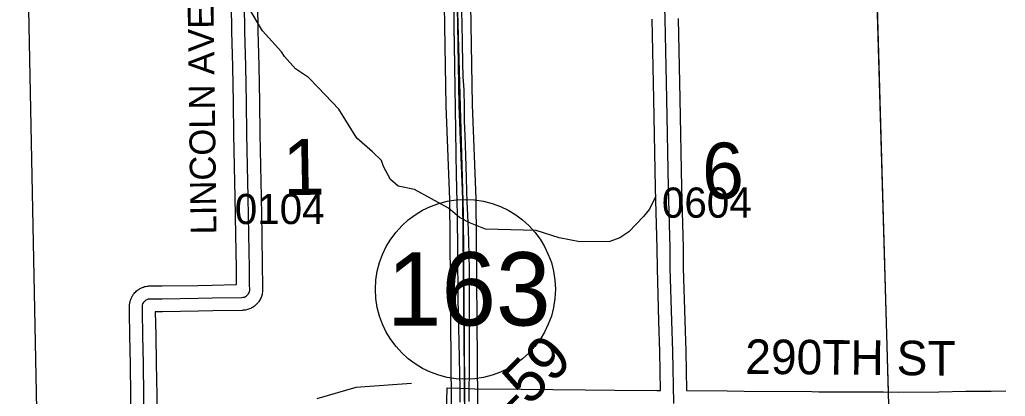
# Model space of a CAD drawing. Extents: x 23.6 to 68.7, y -63 to -29.
# Drawn here: x 43.719 to 46.003, y -52.609 to -51.736 of the extents above; entities that cross this region are included whole.
import ezdxf

# ---------------------------------------------------------------- set-up
doc = ezdxf.new("R2010")
doc.units = 0
for name, color, linetype in [('tdCoDivCarto', 7, 'Continuous'), ('tdCoHydroRiver', 7, 'Continuous'), ('tdCoPriCL', 7, 'Continuous'), ('tdCoPriDiv', 7, 'Continuous'), ('tdCoPrimary', 7, 'Continuous'), ('tdCoSecRdNmbr', 7, 'Continuous'), ('tdCoSecRdTxt', 7, 'Continuous'), ('tdCoSecRteBand', 7, 'Continuous'), ('tdCoSecRteCL', 7, 'Continuous'), ('tdCoSectLine', 7, 'Continuous'), ('tdCoSectLinePart', 7, 'Continuous'), ('tdCoSectNmbr', 7, 'Continuous'), ('tdCoShieldStRte', 7, 'Continuous'), ('tdCoSurfGravel', 7, 'Continuous'), ('tdCoTwpBndryShd', 7, 'Continuous'), ('tdStHwyPriRefPost1', 7, 'Continuous')]:
    doc.layers.add(name, color=color, linetype=linetype)

msp = doc.modelspace()

# ---------------------------------------------------------------- linework, layer by layer
at = {"layer": 'tdCoDivCarto'}
for p, q in [((44.7248, -51.7095), (44.725, -51.754)), ((44.7443, -51.7554), (44.743, -51.7073)), ((44.725, -51.754), (44.7256, -51.7945)), ((44.7447, -51.7798), (44.7443, -51.7554)), ((44.7256, -51.7945), (44.7262, -51.8433)), ((44.745, -51.7922), (44.7447, -51.7798)), ((44.7457, -51.8348), (44.745, -51.7922)), ((44.7262, -51.8433), (44.728, -51.9422)), ((44.7467, -51.8683), (44.7457, -51.8348)), ((44.7484, -51.8982), (44.7467, -51.8683)), ((44.7494, -51.9384), (44.7484, -51.8982)), ((44.7499, -51.9712), (44.7494, -51.9384)), ((44.728, -51.9422), (44.729, -51.9915)), ((44.7509, -52.0042), (44.7499, -51.9712)), ((44.729, -51.9915), (44.7295, -52.0485)), ((44.7524, -52.0508), (44.7509, -52.0042)), ((44.7295, -52.0485), (44.7302, -52.0948)), ((44.7539, -52.1016), (44.7524, -52.0508)), ((44.7302, -52.0948), (44.7314, -52.1587)), ((44.7549, -52.1339), (44.7539, -52.1016)), ((44.7556, -52.1571), (44.7549, -52.1339)), ((44.7314, -52.1587), (44.7322, -52.1885)), ((44.7571, -52.1892), (44.7556, -52.1571)), ((44.7322, -52.1885), (44.7331, -52.2741)), ((44.7588, -52.223), (44.7571, -52.1892)), ((44.7593, -52.2523), (44.7588, -52.223)), ((44.7603, -52.2787), (44.7593, -52.2523)), ((44.7331, -52.2741), (44.7344, -52.3836)), ((44.761, -52.3172), (44.7603, -52.2787)), ((44.7613, -52.3586), (44.761, -52.3172)), ((44.7615, -52.4156), (44.7613, -52.3586)), ((44.7344, -52.3836), (44.7361, -52.4832)), ((44.7613, -52.4745), (44.7615, -52.4156)), ((44.7361, -52.4832), (44.7383, -52.5577)), ((44.7608, -52.5093), (44.7613, -52.4745)), ((44.761, -52.5564), (44.7608, -52.5093)), ((44.7383, -52.5577), (44.7383, -52.5588)), ((44.7383, -52.5588), (44.7385, -52.5887)), ((44.7383, -52.5588), (44.7385, -52.5887)), ((44.7607, -52.5868), (44.761, -52.5606)), ((44.761, -52.5606), (44.761, -52.5564)), ((44.7385, -52.5887), (44.7386, -52.6189)), ((44.7602, -52.6209), (44.7605, -52.598)), ((44.7605, -52.598), (44.7607, -52.5868))]:
    msp.add_line(p, q, dxfattribs=at)
for points in [[(44.7248, -51.7075), (44.725, -51.754), (44.7255, -51.7925)], [(44.7248, -51.7095), (44.725, -51.754), (44.7256, -51.7945)], [(44.7248, -51.7095), (44.725, -51.754), (44.7256, -51.7945)], [(44.745, -51.7922), (44.7447, -51.7798), (44.7443, -51.7554), (44.743, -51.7073)], [(44.745, -51.7922), (44.7447, -51.7798), (44.7443, -51.7554), (44.743, -51.7073)], [(44.745, -51.7922), (44.7447, -51.7798), (44.7443, -51.7554), (44.743, -51.7073)], [(44.7255, -51.7925), (44.7262, -51.8433), (44.728, -51.9422), (44.729, -51.9915), (44.7295, -52.0485), (44.7302, -52.0948), (44.7314, -52.1587), (44.7322, -52.1885), (44.7331, -52.2741), (44.7344, -52.3836), (44.7361, -52.4832), (44.7383, -52.5568)], [(44.7256, -51.7945), (44.7262, -51.8433), (44.728, -51.9422), (44.729, -51.9915), (44.7295, -52.0485), (44.7302, -52.0948), (44.7314, -52.1587), (44.7322, -52.1885), (44.7331, -52.2741), (44.7344, -52.3836), (44.7361, -52.4832), (44.7383, -52.5577), (44.7383, -52.5588)], [(44.7256, -51.7945), (44.7262, -51.8433), (44.728, -51.9422), (44.729, -51.9915), (44.7295, -52.0485), (44.7302, -52.0948), (44.7314, -52.1587), (44.7322, -52.1885), (44.7331, -52.2741), (44.7344, -52.3836), (44.7361, -52.4832), (44.7383, -52.5577), (44.7383, -52.5588)], [(44.761, -52.5564), (44.7608, -52.5093), (44.7613, -52.4745), (44.7615, -52.4156), (44.7613, -52.3586), (44.761, -52.3172), (44.7603, -52.2787), (44.7593, -52.2523), (44.7588, -52.223), (44.7571, -52.1892), (44.7556, -52.1571), (44.7549, -52.1339), (44.7539, -52.1016), (44.7524, -52.0508), (44.7509, -52.0042), (44.7499, -51.9712), (44.7494, -51.9384), (44.7484, -51.8982), (44.7467, -51.8683), (44.7457, -51.8348), (44.745, -51.7922)], [(44.761, -52.5564), (44.7608, -52.5093), (44.7613, -52.4745), (44.7615, -52.4156), (44.7613, -52.3586), (44.761, -52.3172), (44.7603, -52.2787), (44.7593, -52.2523), (44.7588, -52.223), (44.7571, -52.1892), (44.7556, -52.1571), (44.7549, -52.1339), (44.7539, -52.1016), (44.7524, -52.0508), (44.7509, -52.0042), (44.7499, -51.9712), (44.7494, -51.9384), (44.7484, -51.8982), (44.7467, -51.8683), (44.7457, -51.8348), (44.745, -51.7922)], [(44.761, -52.5564), (44.7608, -52.5093), (44.7613, -52.4745), (44.7615, -52.4156), (44.7613, -52.3586), (44.761, -52.3172), (44.7603, -52.2787), (44.7593, -52.2523), (44.7588, -52.223), (44.7571, -52.1892), (44.7556, -52.1571), (44.7549, -52.1339), (44.7539, -52.1016), (44.7524, -52.0508), (44.7509, -52.0042), (44.7499, -51.9712), (44.7494, -51.9384), (44.7484, -51.8982), (44.7467, -51.8683), (44.7457, -51.8348), (44.745, -51.7922)], [(44.7383, -52.5568), (44.7383, -52.5577), (44.7385, -52.5867)], [(44.7383, -52.5588), (44.7385, -52.5887)], [(44.7607, -52.5868), (44.761, -52.5606), (44.761, -52.5564)], [(44.7607, -52.5868), (44.761, -52.5606), (44.761, -52.5564)], [(44.7607, -52.5868), (44.761, -52.5606), (44.761, -52.5564)], [(44.7385, -52.5867), (44.7386, -52.6189), (44.7386, -52.6204), (44.7386, -52.6208)], [(44.7385, -52.5887), (44.7386, -52.6189), (44.7386, -52.6204), (44.7386, -52.6228)], [(44.7385, -52.5887), (44.7386, -52.6189), (44.7386, -52.6204), (44.7386, -52.6228)], [(44.7602, -52.6209), (44.7605, -52.598), (44.7607, -52.5868)], [(44.7602, -52.6209), (44.7605, -52.598), (44.7607, -52.5868)], [(44.7602, -52.6209), (44.7605, -52.598), (44.7607, -52.5868)]]:
    msp.add_lwpolyline(points, dxfattribs=at)
at = {"layer": 'tdCoHydroRiver'}
for points in [[(45.1925, -52.1462), (45.1785, -52.1747), (45.1645, -52.1922), (45.1301, -52.2273), (45.1097, -52.2417), (45.0861, -52.2498), (45.0166, -52.2505), (44.9692, -52.2415), (44.9154, -52.2246), (44.7985, -52.221), (44.7637, -52.2071), (44.7383, -52.1947), (44.7128, -52.1729), (44.6335, -52.1294), (44.5955, -52.1219), (44.578, -52.1063), (44.562, -52.0764), (44.5571, -52.0623), (44.5364, -52.0419), (44.4998, -52.0107), (44.4581, -51.9432), (44.4102, -51.8932), (44.3879, -51.8697), (44.3577, -51.8495), (44.3322, -51.8213), (44.3258, -51.8103), (44.2811, -51.7618), (44.2507, -51.71)], [(44.6267, -52.5794), (44.4974, -52.5885), (44.4076, -52.6146)]]:
    msp.add_lwpolyline(points, dxfattribs=at)
at = {"layer": 'tdCoPriCL'}
msp.add_lwpolyline([(44.7494, -52.6208), (44.7496, -52.5866), (44.7497, -52.5565), (44.7457, -52.152), (44.7374, -51.9343), (44.7349, -51.7923), (44.7335, -51.7075), (44.7331, -51.6832), (44.7329, -51.6732), (44.7327, -51.6638), (44.7295, -51.5918), (44.7293, -51.5829), (44.7295, -51.5421), (44.7294, -51.5134), (44.7261, -51.3307), (44.7248, -51.274), (44.7219, -51.2283), (44.7069, -51.1127)], dxfattribs=at)
at = {"layer": 'tdCoPriDiv'}
for points in [[(44.7744, -55.3467), (44.7731, -54.7043), (44.7731, -54.578), (44.768, -54.3876), (44.7441, -54.1481), (44.7383, -53.8732), (44.7299, -53.6205), (44.72, -52.9192), (44.7194, -52.6207), (44.7158, -52.1528), (44.7074, -51.9351), (44.7002, -51.5156), (44.6948, -51.2752), (44.6921, -51.2312), (44.6796, -51.1348)], [(44.74, -51.1344), (44.7518, -51.2254), (44.7548, -51.2727), (44.7602, -51.5144), (44.7674, -51.9334), (44.7758, -52.1513), (44.7794, -52.6208), (44.78, -52.9184), (44.7899, -53.6189), (44.7983, -53.8716), (44.804, -54.1443), (44.8279, -54.384), (44.8331, -54.5775), (44.8331, -54.7034), (44.8344, -55.3459)]]:
    msp.add_lwpolyline(points, dxfattribs=at)
at = {"layer": 'tdCoPrimary'}
msp.add_line((44.7383, -52.5588), (44.7385, -52.5887), dxfattribs=at)
msp.add_line((44.7383, -52.5588), (44.7385, -52.5887), dxfattribs=at)
for points in [[(44.7248, -51.7095), (44.725, -51.754), (44.7256, -51.7945)], [(44.7248, -51.7095), (44.725, -51.754), (44.7256, -51.7945)], [(44.7248, -51.7095), (44.725, -51.754), (44.7256, -51.7945), (44.7262, -51.8433), (44.728, -51.9422), (44.729, -51.9915), (44.7295, -52.0485), (44.7302, -52.0948), (44.7314, -52.1587), (44.7322, -52.1885), (44.7331, -52.2741), (44.7344, -52.3836), (44.7361, -52.4832), (44.7383, -52.5577), (44.7383, -52.5588), (44.7385, -52.5887), (44.7386, -52.6189)], [(44.745, -51.7922), (44.7447, -51.7798), (44.7443, -51.7554), (44.743, -51.7073)], [(44.745, -51.7922), (44.7447, -51.7798), (44.7443, -51.7554), (44.743, -51.7073)], [(44.7602, -52.6209), (44.7605, -52.598), (44.7607, -52.5868), (44.761, -52.5606), (44.761, -52.5564), (44.7608, -52.5093), (44.7613, -52.4745), (44.7615, -52.4156), (44.7613, -52.3586), (44.761, -52.3172), (44.7603, -52.2787), (44.7593, -52.2523), (44.7588, -52.223), (44.7571, -52.1892), (44.7556, -52.1571), (44.7549, -52.1339), (44.7539, -52.1016), (44.7524, -52.0508), (44.7509, -52.0042), (44.7499, -51.9712), (44.7494, -51.9384), (44.7484, -51.8982), (44.7467, -51.8683), (44.7457, -51.8348), (44.745, -51.7922), (44.7447, -51.7798), (44.7443, -51.7554), (44.743, -51.7073)], [(44.7256, -51.7945), (44.7262, -51.8433), (44.728, -51.9422), (44.729, -51.9915), (44.7295, -52.0485), (44.7302, -52.0948), (44.7314, -52.1587), (44.7322, -52.1885), (44.7331, -52.2741), (44.7344, -52.3836), (44.7361, -52.4832), (44.7383, -52.5577), (44.7383, -52.5588)], [(44.7256, -51.7945), (44.7262, -51.8433), (44.728, -51.9422), (44.729, -51.9915), (44.7295, -52.0485), (44.7302, -52.0948), (44.7314, -52.1587), (44.7322, -52.1885), (44.7331, -52.2741), (44.7344, -52.3836), (44.7361, -52.4832), (44.7383, -52.5577), (44.7383, -52.5588)], [(44.761, -52.5564), (44.7608, -52.5093), (44.7613, -52.4745), (44.7615, -52.4156), (44.7613, -52.3586), (44.761, -52.3172), (44.7603, -52.2787), (44.7593, -52.2523), (44.7588, -52.223), (44.7571, -52.1892), (44.7556, -52.1571), (44.7549, -52.1339), (44.7539, -52.1016), (44.7524, -52.0508), (44.7509, -52.0042), (44.7499, -51.9712), (44.7494, -51.9384), (44.7484, -51.8982), (44.7467, -51.8683), (44.7457, -51.8348), (44.745, -51.7922)], [(44.761, -52.5564), (44.7608, -52.5093), (44.7613, -52.4745), (44.7615, -52.4156), (44.7613, -52.3586), (44.761, -52.3172), (44.7603, -52.2787), (44.7593, -52.2523), (44.7588, -52.223), (44.7571, -52.1892), (44.7556, -52.1571), (44.7549, -52.1339), (44.7539, -52.1016), (44.7524, -52.0508), (44.7509, -52.0042), (44.7499, -51.9712), (44.7494, -51.9384), (44.7484, -51.8982), (44.7467, -51.8683), (44.7457, -51.8348), (44.745, -51.7922)], [(44.7607, -52.5868), (44.761, -52.5606), (44.761, -52.5564)], [(44.7607, -52.5868), (44.761, -52.5606), (44.761, -52.5564)], [(44.7385, -52.5887), (44.7386, -52.6189), (44.7386, -52.6204), (44.7386, -52.6228)], [(44.7385, -52.5887), (44.7386, -52.6189), (44.7386, -52.6204), (44.7386, -52.6228)], [(44.7602, -52.6209), (44.7605, -52.598), (44.7607, -52.5868)], [(44.7602, -52.6209), (44.7605, -52.598), (44.7607, -52.5868)]]:
    msp.add_lwpolyline(points, dxfattribs=at)
at = {"layer": 'tdCoSecRteBand'}
for points in [[(43.9772, -52.6857), (43.9762, -52.6076), (43.9753, -52.5338), (43.9739, -52.4686), (43.9739, -52.4686), (43.9739, -52.4685), (43.973, -52.413), (43.9729, -52.4122), (43.973, -52.4114), (43.9735, -52.3966), (43.9736, -52.3929), (43.9746, -52.3893), (43.9755, -52.3864), (43.9761, -52.3841), (43.9772, -52.3818), (43.9785, -52.3791), (43.9795, -52.3769), (43.9809, -52.3749), (43.9827, -52.3724), (43.9841, -52.3704), (43.9858, -52.3686), (43.9879, -52.3665), (43.9896, -52.3647), (43.9916, -52.3632), (43.994, -52.3614), (43.996, -52.36), (43.9982, -52.3589), (44.0009, -52.3575), (44.003, -52.3564), (44.0054, -52.3556), (44.0083, -52.3547), (44.0106, -52.354), (44.013, -52.3536), (44.016, -52.3532), (44.0182, -52.3528), (44.0204, -52.3528), (44.0488, -52.3528), (44.1318, -52.3517), (44.1651, -52.351), (44.1651, -52.351), (44.1651, -52.351), (44.2215, -52.3499), (44.2215, -52.3485), (44.221, -52.3115), (44.2196, -52.2341), (44.2196, -52.2341), (44.2196, -52.2341), (44.2181, -52.1478), (44.2168, -52.076), (44.2153, -52.0012), (44.2153, -52.0011), (44.2153, -52.001), (44.2143, -51.9281), (44.2127, -51.8441), (44.2107, -51.7631), (44.2107, -51.763), (44.2107, -51.7628), (44.2097, -51.7001)], [(44.2697, -51.6991), (44.2707, -51.7618), (44.2726, -51.8427), (44.2726, -51.8428), (44.2726, -51.8428), (44.2743, -51.927), (44.2743, -51.9271), (44.2743, -51.9272), (44.2753, -52.0001), (44.2768, -52.0748), (44.2768, -52.0748), (44.2768, -52.0749), (44.2781, -52.1467), (44.2781, -52.1467), (44.2781, -52.1467), (44.2796, -52.233), (44.281, -52.3104), (44.281, -52.3105), (44.281, -52.3106), (44.2815, -52.3477), (44.2815, -52.3478), (44.2815, -52.3478), (44.2817, -52.3633), (44.2817, -52.3666), (44.281, -52.3699), (44.2804, -52.3728), (44.2799, -52.3751), (44.2791, -52.3773), (44.278, -52.38), (44.2771, -52.3822), (44.2759, -52.3843), (44.2745, -52.3868), (44.2733, -52.3889), (44.2718, -52.3907), (44.2699, -52.393), (44.2684, -52.3948), (44.2667, -52.3964), (44.2645, -52.3983), (44.2627, -52.3999), (44.2607, -52.4012), (44.2582, -52.4028), (44.2562, -52.4041), (44.2541, -52.405), (44.2514, -52.4062), (44.2492, -52.4071), (44.2469, -52.4077), (44.2441, -52.4085), (44.2418, -52.4091), (44.2394, -52.4093), (44.2365, -52.4096), (44.2353, -52.4097), (44.2342, -52.4097), (44.1663, -52.411), (44.1329, -52.4117), (44.1328, -52.4117), (44.1328, -52.4117), (44.0494, -52.4128), (44.0492, -52.4128), (44.049, -52.4128), (44.033, -52.4128), (44.0339, -52.4674), (44.0352, -52.5327), (44.0353, -52.5328), (44.0353, -52.5329), (44.0362, -52.6068), (44.0362, -52.6069), (44.0362, -52.6069), (44.0372, -52.685)], [(45.2447, -51.733), (45.2483, -51.9188), (45.2524, -52.1244), (45.2524, -52.1244), (45.2524, -52.1244), (45.2529, -52.1525), (45.256, -52.2648), (45.256, -52.265), (45.256, -52.2653), (45.2565, -52.3112), (45.2601, -52.4328), (45.2601, -52.4328), (45.2601, -52.4328), (45.2622, -52.5044), (45.2622, -52.5046), (45.2622, -52.5047), (45.2639, -52.5949), (45.2639, -52.5949), (45.2639, -52.5954), (45.3581, -52.5961), (45.3583, -52.5961), (45.3585, -52.5961), (45.3978, -52.5969), (45.5546, -52.5982), (45.5546, -52.5982), (45.5547, -52.5982), (45.5705, -52.5984), (45.7202, -52.5987), (45.7203, -52.5987), (45.7204, -52.5987), (45.7547, -52.5991), (45.8486, -52.5984), (45.911, -52.5974), (45.9112, -52.5974), (45.9115, -52.5974), (45.9703, -52.5974), (46.0041, -52.5963)], [(44.7076, -52.6492), (44.7097, -52.5893), (44.7397, -52.5904), (44.7613, -52.5912), (44.7733, -52.5916), (44.8819, -52.5927), (44.9545, -52.5931), (44.9545, -52.5931), (44.9546, -52.5931), (45.029, -52.5938), (45.0291, -52.5938), (45.0291, -52.5938), (45.0983, -52.5946), (45.1953, -52.5958), (45.2039, -52.5958), (45.2022, -52.506), (45.2001, -52.4346), (45.1965, -52.3127), (45.1965, -52.3124), (45.1965, -52.3121), (45.196, -52.2662), (45.1929, -52.154), (45.1929, -52.1539), (45.1929, -52.1537), (45.1924, -52.1255), (45.1883, -51.92), (45.1883, -51.92), (45.1883, -51.92), (45.1847, -51.7343)]]:
    msp.add_lwpolyline(points, dxfattribs=at)
at = {"layer": 'tdCoSecRteCL'}
for points in [[(45.2346, -52.6255), (45.2345, -52.6244), (45.2322, -52.5053), (45.2301, -52.4337), (45.2265, -52.3118), (45.226, -52.2656), (45.2229, -52.1532), (45.2224, -52.1249), (45.2183, -51.9194), (45.2147, -51.7336), (45.2124, -51.6579), (45.2104, -51.5986), (45.2075, -51.5621), (45.2063, -51.5424), (45.2047, -51.4862), (45.2045, -51.4518)], [(44.0072, -52.6853), (44.0062, -52.6072), (44.0053, -52.5333), (44.0039, -52.468), (44.003, -52.4124), (44.0034, -52.3976), (44.0043, -52.3947), (44.0056, -52.392), (44.0073, -52.3895), (44.0094, -52.3874), (44.0118, -52.3856), (44.0145, -52.3842), (44.0174, -52.3833), (44.0204, -52.3828), (44.049, -52.3828), (44.1323, -52.3817), (44.1657, -52.381), (44.2336, -52.3797), (44.2365, -52.3794), (44.2394, -52.3787), (44.242, -52.3775), (44.2445, -52.3759), (44.2467, -52.374), (44.2486, -52.3717), (44.25, -52.3692), (44.2511, -52.3665), (44.2517, -52.3636), (44.2515, -52.3481), (44.251, -52.311), (44.2496, -52.2336), (44.2481, -52.1472), (44.2468, -52.0754), (44.2453, -52.0006), (44.2443, -51.9276), (44.2427, -51.8434), (44.2407, -51.7624), (44.2397, -51.6996)]]:
    msp.add_lwpolyline(points, dxfattribs=at)
at = {"layer": 'tdCoSectLine'}
for points in [[(45.7019, -51.569), (45.7323, -52.6288)], [(43.7365, -51.5949), (43.7576, -52.6387)], [(44.7293, -51.5796), (44.7461, -52.184), (44.7494, -52.6207)]]:
    msp.add_lwpolyline(points, dxfattribs=at)
at = {"layer": 'tdCoSectLinePart'}
for points in [[(43.7365, -51.5949), (43.7576, -52.6387)], [(44.7293, -51.5796), (44.7461, -52.184), (44.7492, -52.5907)], [(45.7024, -51.5873), (45.7314, -52.5989)]]:
    msp.add_lwpolyline(points, dxfattribs=at)
at = {"layer": 'tdCoShieldStRte'}
msp.add_circle((44.7517, -52.3609), 0.2085, dxfattribs=at)
at = {"layer": 'tdCoSurfGravel'}
for points in [[(45.2345, -52.6244), (45.2322, -52.5053), (45.2301, -52.4337), (45.2265, -52.3118), (45.226, -52.2656), (45.2229, -52.1532), (45.2224, -52.1249), (45.2183, -51.9194), (45.2147, -51.7336), (45.2124, -51.6579), (45.2104, -51.5986), (45.2075, -51.5621), (45.2063, -51.5424), (45.2047, -51.4862), (45.2045, -51.4518), (45.2044, -51.4505)], [(44.0072, -52.6853), (44.0062, -52.6072), (44.0053, -52.5333), (44.0039, -52.468), (44.003, -52.4124), (44.0034, -52.3976), (44.0043, -52.3947), (44.0056, -52.392), (44.0073, -52.3895), (44.0094, -52.3874), (44.0118, -52.3856), (44.0145, -52.3842), (44.0174, -52.3833), (44.0204, -52.3828), (44.049, -52.3828), (44.1323, -52.3817), (44.1657, -52.381), (44.2336, -52.3797), (44.2365, -52.3794), (44.2394, -52.3787), (44.242, -52.3775), (44.2445, -52.3759), (44.2467, -52.374), (44.2486, -52.3717), (44.25, -52.3692), (44.2511, -52.3665), (44.2517, -52.3636), (44.2515, -52.3481), (44.251, -52.311), (44.2496, -52.2336), (44.2481, -52.1472), (44.2468, -52.0754), (44.2453, -52.0006), (44.2443, -51.9276), (44.2427, -51.8434), (44.2407, -51.7624), (44.2397, -51.6996)]]:
    msp.add_lwpolyline(points, dxfattribs=at)
at = {"layer": 'tdCoTwpBndryShd'}
msp.add_lwpolyline([(43.7188, -49.8441), (43.7206, -50.071), (44.5531, -50.0557), (44.5706, -50.1659), (44.6521, -50.5976), (44.7246, -51.0894), (44.7293, -51.5796), (44.7461, -52.184), (44.7494, -52.6207), (44.7599, -53.6197), (44.7866, -54.6214), (44.8089, -55.6241), (44.8037, -55.6224), (44.8037, -55.6241), (44.8059, -56.6231), (44.8305, -57.6351)], dxfattribs=at)

# ---------------------------------------------------------------- texts
at = {"layer": 'tdCoSecRdNmbr'}
for s, rotation, p in [('0104', 0.0345, (44.2172, -52.2096)), ('0604', 0.0352, (45.207, -52.1948))]:
    msp.add_text(s, height=0.07, rotation=rotation, dxfattribs=at).set_placement(p)
at = {"layer": 'tdCoSecRdTxt'}
for s, height, rotation, p in [('LINCOLN AVE', 0.06, 90.7435, (44.1749, -52.2333)), ('290TH ST', 0.08, 359.5017, (45.3999, -52.5568))]:
    msp.add_text(s, height=height, rotation=rotation, dxfattribs=at).set_placement(p)
at = {"layer": 'tdCoSectNmbr'}
for s, rotation, p in [('1', 1.0345, (44.3297, -52.1429)), ('6', 1.0352, (45.3012, -52.1516))]:
    msp.add_text(s, height=0.13, rotation=rotation, dxfattribs=at).set_placement(p)
at = {"layer": 'tdCoShieldStRte'}
msp.add_text('163', height=0.17, dxfattribs=at).set_placement((44.5697, -52.4448))
at = {"layer": 'tdStHwyPriRefPost1'}
msp.add_text('‒‒59', height=0.1, rotation=45, dxfattribs=at).set_placement((44.794, -52.7386))

doc.saveas('drawing.dxf')
